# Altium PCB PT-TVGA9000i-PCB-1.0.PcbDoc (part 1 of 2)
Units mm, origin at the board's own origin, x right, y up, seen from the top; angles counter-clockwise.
Board outline 80.1 x 47 mm, 4 copper layers (Top Layer, Layer 1, Layer 2, Bottom Layer), stack 0.603 mm thick; 67 components, 130 nets, 468 pads, 340 vias.
Unrouted connection lines stored in the file: 9.
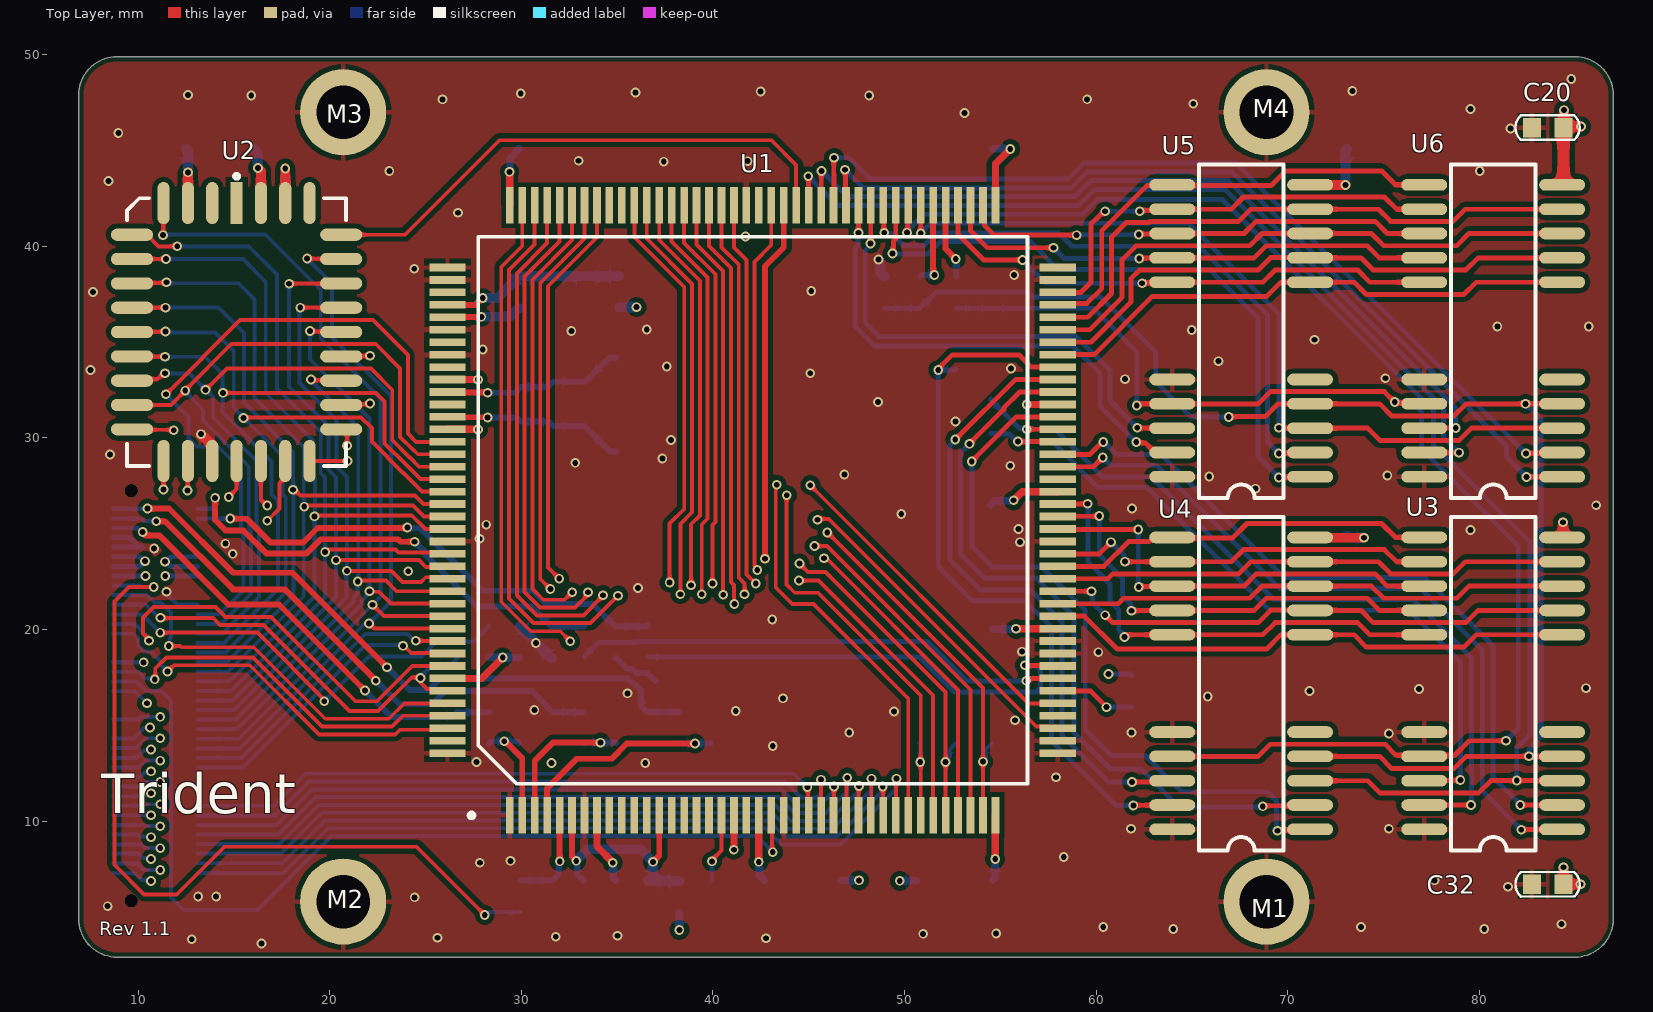
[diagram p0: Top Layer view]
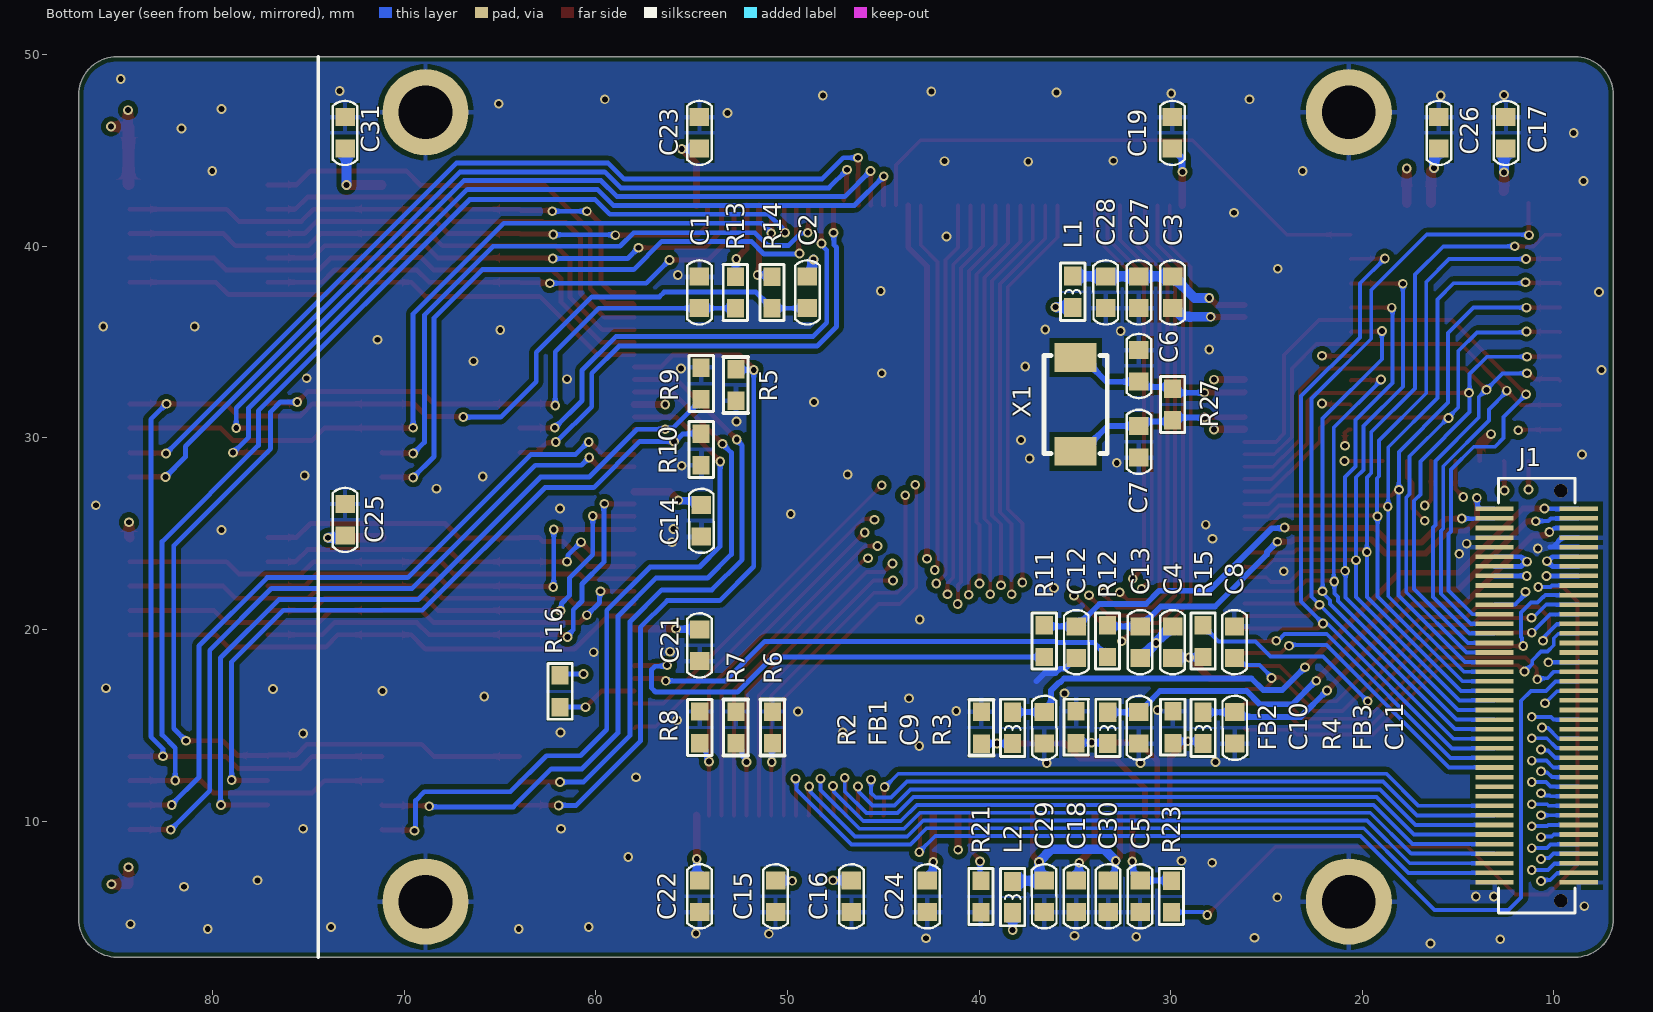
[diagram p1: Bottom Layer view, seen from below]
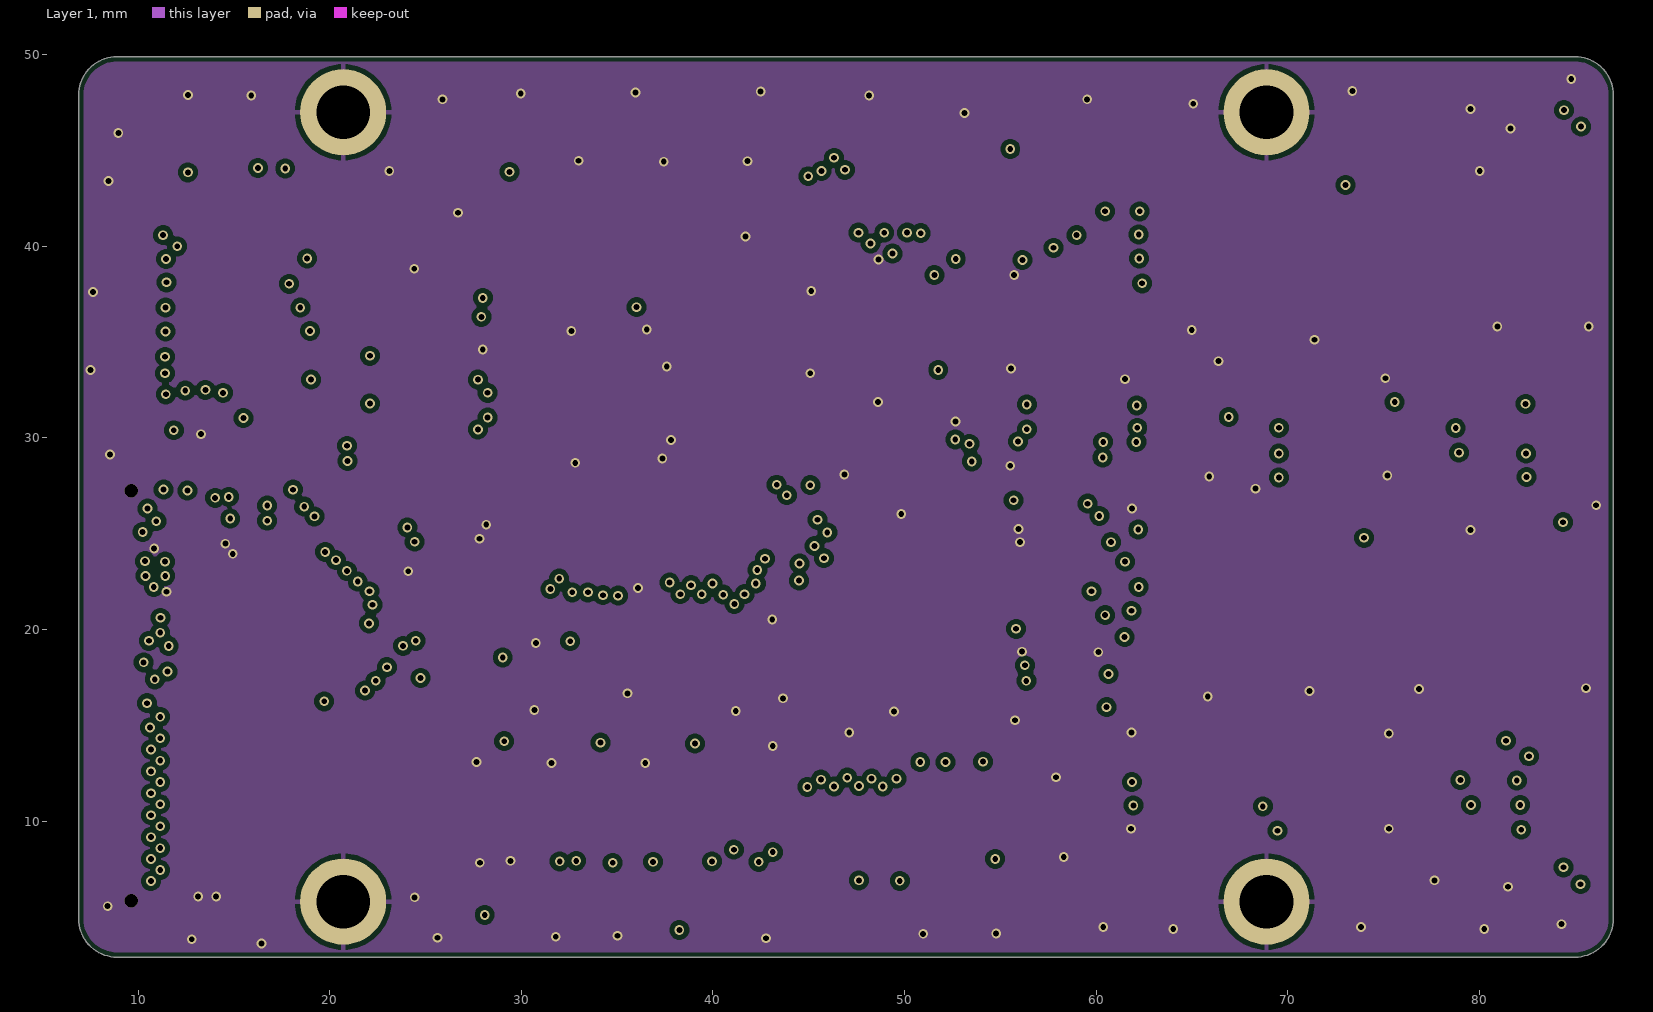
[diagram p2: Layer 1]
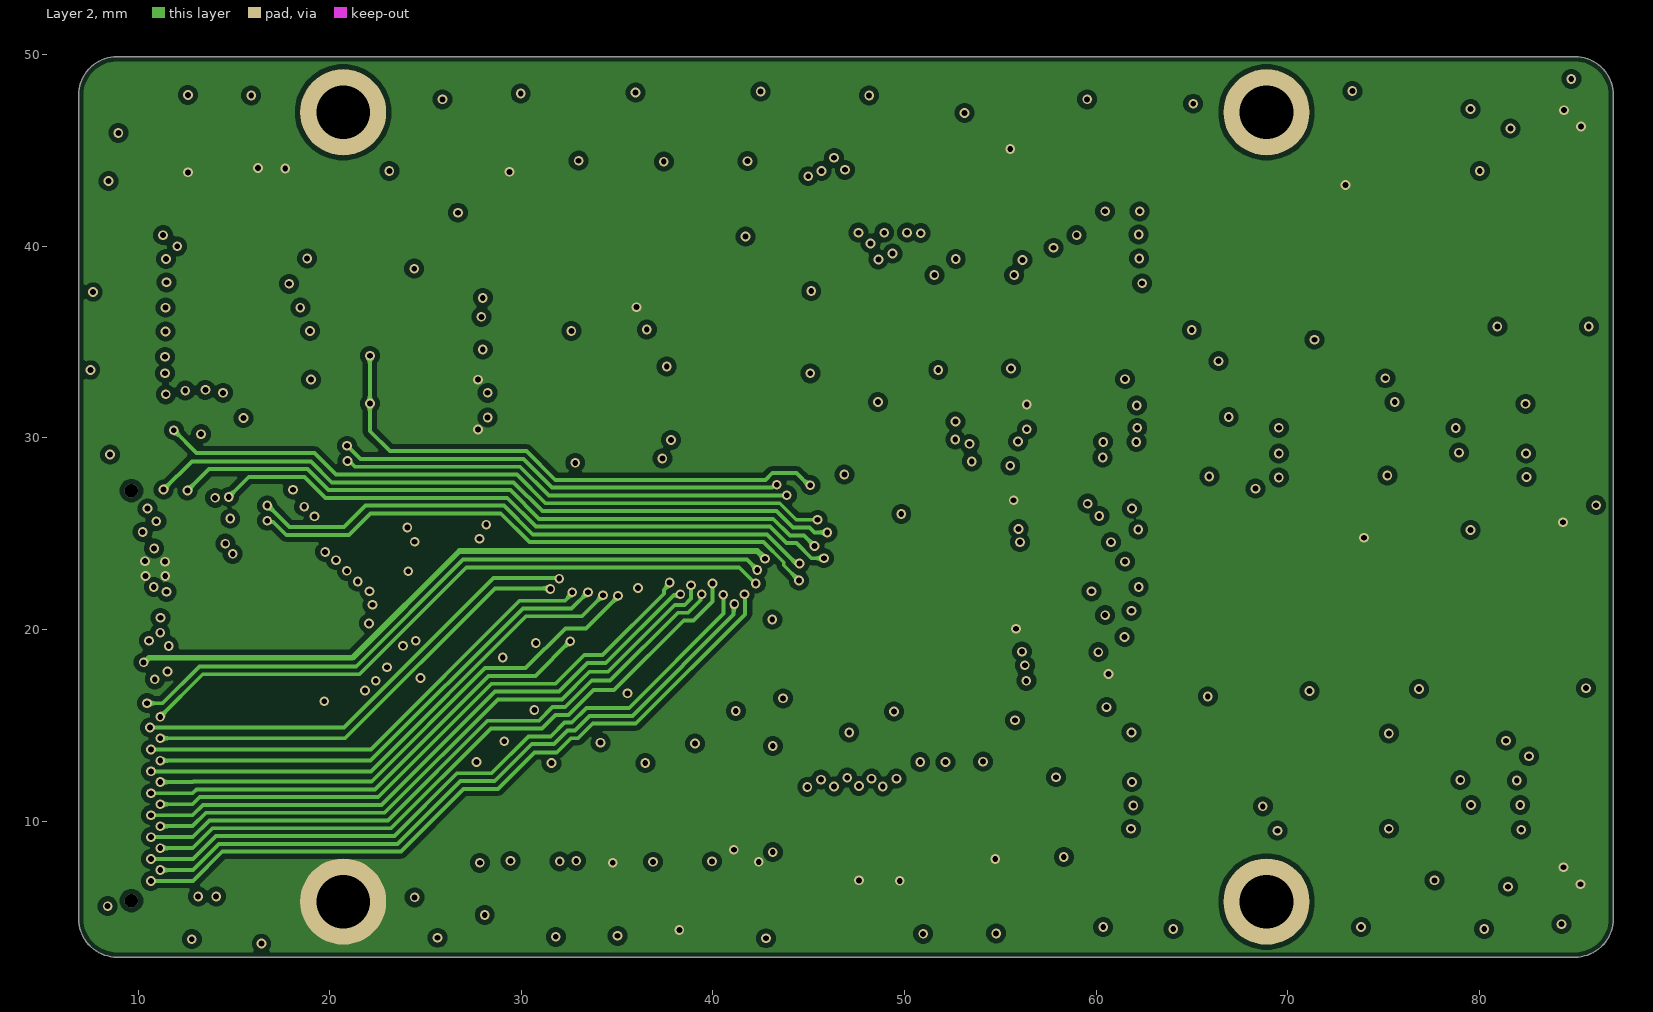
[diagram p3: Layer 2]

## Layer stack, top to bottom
Top Solder: solder mask 0.0102, Solder Resist, Dk 3.5
Top Layer: signal copper 0.0356
Dielectric 2: prepreg 0.0711, PP-006, Dk 4.1
Layer 1: signal copper 0.035
Dielectric 1: dielectric 0.32, FR-4, Dk 4.8
Layer 2: signal copper 0.035
Dielectric 3: prepreg 0.0711, PP-006, Dk 4.1
Bottom Layer: signal copper 0.0356
Bottom Solder: solder mask 0.0102, Solder Resist, Dk 3.5

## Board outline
6.9,4.9 6.9,47.9 cw(c8.9,47.9) 8.9,49.9 85,49.9 cw(c85,47.9) 87,47.9 87,4.9 cw(c85,4.9) 85,2.9 8.9,2.9 cw(c8.9,4.9)

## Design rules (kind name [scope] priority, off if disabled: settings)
BoardOutlineClearance [All] p1: gap=0 ignorepadtopadclearanceinfootprint=FALSE except(0.254: Poly-OutlineEdge)
Clearance [All] p1: gap=0.203 ignorepadtopadclearanceinfootprint=TRUE except(0.254: Arc-Fill Arc-Poly Arc-Region Track-Fill Track-Poly Track-Region SMDPad-Fill SMDPad-Poly SMDPad-Region THPad-Fill THPad-Poly THPad-Region Via-Fill Via-Poly Via-Region Fill-Fill Fill-Poly Fill-Region Poly-Poly Poly-Region Region-Region)
ComponentClearance [All] p1: gap=0 collisioncheckmode=3 verticalgap=0 showdistances=FALSE
HoleSize [All] p1: absolutevalues=TRUE maxlimit=254 minlimit=0.025 maxpercent=80.000 minpercent=20.000
MinimumSolderMaskSliver [All] p1: minsoldermaskwidth=0
PolygonConnect [All] p1: thpad.connectstyle=Relief thpad.reliefconductorwidth=0.254 thpad.reliefentries=4 thpad.polygonreliefangle="90 Angle" thpad.airgapwidth=0.254 smdpad.connectstyle=Relief smdpad.reliefconductorwidth=0.254 smdpad.reliefentries=4 smdpad.polygonreliefangle="90 Angle" smdpad.airgapwidth=0.254 via.connectstyle=Direct via.reliefconductorwidth=0.254 via.reliefentries=4 via.polygonreliefangle="90 Angle" via.airgapwidth=0.254
RoutingVias [All] p1: holewidth=0.711 width=1.27 viastyle="Through Hole" minholewidth=0.305 minwidth=0.508 maxholewidth=0.711 maxwidth=1.27
SilkToSilkClearance [All] p1: silktosilkclearance=0
SilkToSolderMaskClearance [IsPad] p1: minsilkscreentomaskgap=0 clearancetoexposedcopper=TRUE
SolderMaskExpansion [All] p1: expansion=0.102 istentingtop=FALSE
Width [All] p1: maxlimit=5.08 minlimit=0.203 preferedwidth=0.254 midlayer1_maxwidth=1.27 midlayer2_maxwidth=1.27 minimp=50.000000 maximp=50.000000 favimp=50.000000
25 further rules are at their usual default settings.

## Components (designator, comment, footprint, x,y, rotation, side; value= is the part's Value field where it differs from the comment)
C1 "47pf" C0603 54.6,36.774 r90 bottom
C2 "47pf" C0603 48.963,36.774 r90 bottom
C3 "0.1uf" C0603 29.905,38.424 r270 bottom
C4 "47pf" C0603 29.896,20.167 r270 bottom
C5 "470pf" C0603 31.6,6.9 r270 bottom
C6 "5pf" C0603 31.659,34.586 r270 bottom
C7 "5pf" C0603 31.666,28.973 r90 bottom
C8 "47pf" C0603 26.67,18.517 r90 bottom
C9 "47pf" C0603 36.597,15.696 r270 bottom
C10 "47pf" C0603 31.659,15.696 r270 bottom
C11 "47pf" C0603 26.652,15.696 r270 bottom
C12 "47pf" C0603 34.925,20.167 r270 bottom
C13 "47pf" C0603 31.598,20.167 r270 bottom
C14 "0.1uf" C0603 54.5,26.5 r270 bottom
C15 "10uf" C0603 50.629,6.9 r270 bottom
C16 "10uf" C0603 46.665,6.9 r270 bottom
C17 "10uf" C0603 12.5,45.1 r90 bottom
C18 "0.1uf" C0603 34.933,6.9 r270 bottom
C19 "0.1uf" C0603 29.911,45.1 r90 bottom
C20 "0.1uf" C0603 84.4,46.2 r180 top
C21 "0.1uf" C0603 54.594,20 r270 bottom
C22 "0.1uf" C0603 54.594,6.9 r270 bottom
C23 "0.1uf" C0603 54.6,45.1 r90 bottom
C24 "0.1uf" C0603 42.7,6.9 r270 bottom
C25 "0.1uf" C0603 73.1,24.9 r90 bottom
C26 "0.1uf" C0603 16,45.1 r90 bottom
C27 "0.1uf" C0603 31.659,38.424 r270 bottom
C28 "10uf" C0603 33.39,38.424 r270 bottom
C29 "0.1uf" C0603 36.6,6.9 r270 bottom
C30 "10uf" C0603 33.267,6.9 r270 bottom
C31 "0.1uf" C0603 73.1,45.1 r90 bottom
C32 "0.1uf" C0603 84.4,6.7 r180 top
FB1 "68R 100MHz" L0603 38.253,14.865 r270 bottom
FB2 "68R 100Mhz" L0603 33.281,14.865 r270 bottom
FB3 "68R 100Mhz" L0603 28.308,14.865 r270 bottom
J1 "CON40x2" BTB0.5-80P 8.9,6.8 r90 bottom locked
L1 "4.7uH" L0603 35.117,37.63 r270 bottom
L2 "4.7uH" L0603 38.253,6.037 r270 bottom
M1 "CON1" M2.5 68.9,5.8 r0 top locked
M2 "CON1" M2.5 20.7,5.8 r0 top locked
M3 "CON1" M2.5 20.7,47 r0 top locked
M4 "CON1" M2.5 68.9,47 r0 top
R2 "75" R0603 39.884,15.702 r270 bottom
R3 "75" R0603 34.937,15.728 r270 bottom
R4 "75" R0603 29.892,15.728 r270 bottom
R5 "4.7k" R0603 52.7,33.6 r270 bottom
R6 "4.7k" R0603 50.787,14.071 r90 bottom
R7 "4.7k" R0603 52.7,14.071 r90 bottom
R8 "4.7k" R0603 54.585,14.072 r90 bottom
R9 "4.7k" R0603 54.508,32.026 r90 bottom
R10 "4.7k" R0603 54.508,30.226 r270 bottom
R11 "33" R0603 36.601,18.567 r90 bottom
R12 "33" R0603 33.299,18.567 r90 bottom
R13 "33" R0603 52.725,36.773 r90 bottom
R14 "33" R0603 50.813,36.773 r90 bottom
R15 "75" R0603 28.309,18.567 r90 bottom
R16 "4.7k" R0603 61.874,15.951 r90 bottom
R21 "150" R0603 39.91,5.249 r90 bottom
R23 "1k" R0603 29.965,6.9 r270 bottom
R27 "1M" R0603 29.903,30.929 r90 bottom
U1 "TVGA9000i" QFP160 29.4,10.3 r90 top locked
U2 "29C512_PLCC32" PLCC32S 15.139,42.261 r0 top
U3 "MT4C4256" SOJ-20 84.334,9.568 r180 top locked
U4 "MT4C4256" SOJ-20 71.177,9.568 r180 top locked
U5 "MT4C4256" SOJ-20 71.177,27.972 r180 top locked
U6 "MT4C4256" SOJ-20 84.334,27.972 r180 top locked
X1 "40M" 5032 33.313,29.195 r90 bottom

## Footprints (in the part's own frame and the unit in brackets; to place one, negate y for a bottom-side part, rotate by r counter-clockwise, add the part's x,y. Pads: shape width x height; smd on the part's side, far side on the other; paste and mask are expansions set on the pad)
5032 [mm]
  rect 1.5x2.2 smd: 1(0.108,1.651) 2(5.008,1.651)
  silkscreen extent 0,0 5.11,3.3
BTB0.5-80P [mm]
  rect 0.24x2 smd: 1(0,-0.2) 2(0,4.2) 3(0.5,-0.2) 4(0.5,4.2) 5(1,-0.2) 6(1,4.2) 7(1.5,-0.2) 8(1.5,4.2) 9(2,-0.2) 10(2,4.2) 11(2.5,-0.2) 12(2.5,4.2) 13(3,-0.2) 14(3,4.2) 15(3.5,-0.2) 16(3.5,4.2) 17(4,-0.2) 18(4,4.2) 19(4.5,-0.2) 20(4.5,4.2) 21(5,-0.2) 22(5,4.2) 23(5.5,-0.2) 24(5.5,4.2) 25(6,-0.2) 26(6,4.2) 27(6.5,-0.2) 28(6.5,4.2) 29(7,-0.2) 30(7,4.2) 31(7.5,-0.2) 32(7.5,4.2) 33(8,-0.2) 34(8,4.2) 35(8.5,-0.2) 36(8.5,4.2) 37(9,-0.2) 38(9,4.2) 39(9.5,-0.2) 40(9.5,4.2) 41(10,-0.2) 42(10,4.2) 43(10.5,-0.2) 44(10.5,4.2) 45(11,-0.2) 46(11,4.2) 47(11.5,-0.2) 48(11.5,4.2) 49(12,-0.2) 50(12,4.2) 51(12.5,-0.2) 52(12.5,4.2) 53(13,-0.2) 54(13,4.2) 55(13.5,-0.2) 56(13.5,4.2) 57(14,-0.2) 58(14,4.2) 59(14.5,-0.2) 60(14.5,4.2) 61(15,-0.2) 62(15,4.2) 63(15.5,-0.2) 64(15.5,4.2) 65(16,-0.2) 66(16,4.2) 67(16.5,-0.2) 68(16.5,4.2) 69(17,-0.2) 70(17,4.2) 71(17.5,-0.2) 72(17.5,4.2) 73(18,-0.2) 74(18,4.2) 75(18.5,-0.2) 76(18.5,4.2) 77(19,-0.2) 78(19,4.2) 79(19.5,-0.2) 80(19.5,4.2)
  silkscreen extent -1.6,0 21.1,4
C0603 [mil]
  rect 37.01x40 smd: 1(0,0)
  rect 37x40 smd: 2(64.98,0)
  silkscreen extent -34,-25 98,25
L0603 [mm]
  rect 1x0.9 smd: 1(-0.82,0) 2(0.82,0)
  silkscreen extent -1.5,-0.64 1.5,0.64
M2.5 [mm]
  round 4.5 hole 2.8: 1(0,0)
PLCC32S [mil]
  rect 25x86.61 smd: 1(0,0)
  oval 25x86.61 smd: 2(-50,0) 3(-100,0) 4(-150,0) 14(-150,-530) 15(-100,-530) 16(-50,-530) 17(0,-530) 18(50,-530) 19(100,-530) 20(150,-530) 30(150,0) 31(100,0) 32(50,0)
  oval 86.61x25 smd: 5(-215,-65) 6(-215,-115) 7(-215,-165) 8(-215,-215) 9(-215,-265) 10(-215,-315) 11(-215,-365) 12(-215,-415) 13(-215,-465) 21(215,-465) 22(215,-415) 23(215,-365) 24(215,-315) 25(215,-265) 26(215,-215) 27(215,-165) 28(215,-115) 29(215,-65)
  silkscreen extent -225,-540 225,60
QFP160 [mm] "160-Pin Plastic Quad Flat Pack (PQFP)"
  rect 1.9x0.4 smd: 1(0,0) 2(0,-0.65) 3(0,-1.3) 4(0,-1.95) 5(0,-2.6) 6(0,-3.25) 7(0,-3.9) 8(0,-4.55) 9(0,-5.2) 10(0,-5.85) 11(0,-6.5) 12(0,-7.15) 13(0,-7.8) 14(0,-8.45) 15(0,-9.1) 16(0,-9.75) 17(0,-10.4) 18(0,-11.05) 19(0,-11.7) 20(0,-12.35) 21(0,-13) 22(0,-13.65) 23(0,-14.3) 24(0,-14.95) 25(0,-15.6) 26(0,-16.25) 27(0,-16.9) 28(0,-17.55) 29(0,-18.2) 30(0,-18.85) 31(0,-19.5) 32(0,-20.15) 33(0,-20.8) 34(0,-21.45) 35(0,-22.1) 36(0,-22.75) 37(0,-23.4) 38(0,-24.05) 39(0,-24.7) 40(0,-25.35) 81(31.85,-25.35) 82(31.85,-24.7) 83(31.85,-24.05) 84(31.85,-23.4) 85(31.85,-22.75) 86(31.85,-22.1) 87(31.85,-21.45) 88(31.85,-20.8) 89(31.85,-20.15) 90(31.85,-19.5) 91(31.85,-18.85) 92(31.85,-18.2) 93(31.85,-17.55) 94(31.85,-16.9) 95(31.85,-16.25) 96(31.85,-15.6) 97(31.85,-14.95) 98(31.85,-14.3) 99(31.85,-13.65) 100(31.85,-13) 101(31.85,-12.35) 102(31.85,-11.7) 103(31.85,-11.05) 104(31.85,-10.4) 105(31.85,-9.75) 106(31.85,-9.1) 107(31.85,-8.45) 108(31.85,-7.8) 109(31.85,-7.15) 110(31.85,-6.5) 111(31.85,-5.85) 112(31.85,-5.2) 113(31.85,-4.55) 114(31.85,-3.9) 115(31.85,-3.25) 116(31.85,-2.6) 117(31.85,-1.95) 118(31.85,-1.3) 119(31.85,-0.65) 120(31.85,0)
  rect 0.4x1.9 smd: 41(3.25,-28.6) 42(3.9,-28.6) 43(4.55,-28.6) 44(5.2,-28.6) 45(5.85,-28.6) 46(6.5,-28.6) 47(7.15,-28.6) 48(7.8,-28.6) 49(8.45,-28.6) 50(9.1,-28.6) 51(9.75,-28.6) 52(10.4,-28.6) 53(11.05,-28.6) 54(11.7,-28.6) 55(12.35,-28.6) 56(13,-28.6) 57(13.65,-28.6) 58(14.3,-28.6) 59(14.95,-28.6) 60(15.6,-28.6) 61(16.25,-28.6) 62(16.9,-28.6) 63(17.55,-28.6) 64(18.2,-28.6) 65(18.85,-28.6) 66(19.5,-28.6) 67(20.15,-28.6) 68(20.8,-28.6) 69(21.45,-28.6) 70(22.1,-28.6) 71(22.75,-28.6) 72(23.4,-28.6) 73(24.05,-28.6) 74(24.7,-28.6) 75(25.35,-28.6) 76(26,-28.6) 77(26.65,-28.6) 78(27.3,-28.6) 79(27.95,-28.6) 80(28.6,-28.6) 121(28.6,3.25) 122(27.95,3.25) 123(27.3,3.25) 124(26.65,3.25) 125(26,3.25) 126(25.35,3.25) 127(24.7,3.25) 128(24.05,3.25) 129(23.4,3.25) 130(22.75,3.25) 131(22.1,3.25) 132(21.45,3.25) 133(20.8,3.25) 134(20.15,3.25) 135(19.5,3.25) 136(18.85,3.25) 137(18.2,3.25) 138(17.55,3.25) 139(16.9,3.25) 140(16.25,3.25) 141(15.6,3.25) 142(14.95,3.25) 143(14.3,3.25) 144(13.65,3.25) 145(13,3.25) 146(12.35,3.25) 147(11.7,3.25) 148(11.05,3.25) 149(10.4,3.25) 150(9.75,3.25) 151(9.1,3.25) 152(8.45,3.25) 153(7.8,3.25) 154(7.15,3.25) 155(6.5,3.25) 156(5.85,3.25) 157(5.2,3.25) 158(4.55,3.25) 159(3.9,3.25) 160(3.25,3.25)
  silkscreen extent -0.12,-27.03 30.2,2.12
R0603 [mil]
  rect 38x35 smd: 1(0,0) 2(65,0)
  silkscreen extent -25,-25 90,25
SOJ-20 [mm] "薄贴片"
  oval 2.4x0.61 smd: 1(0,0) 2(0,-1.27) 3(0,-2.54) 4(0,-3.81) 5(0,-5.08) 6(0,-10.16) 7(0,-11.43) 8(0,-12.7) 9(0,-13.97) 10(0,-15.24) 11(7.2,-15.24) 12(7.2,-13.97) 13(7.2,-12.7) 14(7.2,-11.43) 15(7.2,-10.16) 16(7.2,-5.08) 17(7.2,-3.81) 18(7.2,-2.54) 19(7.2,-1.27) 20(7.2,0)
  silkscreen extent 1.4,-16.3 5.8,1.1

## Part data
C1 C2: library part 0CAP
C3 C4 C5 C6 C7 C8 C9 C10 C11 C12 C13 C14 C15 C16 C17 C18 C19 C20 C21 C22 C23 C24 C25 C26 C27 C28 C29 C30 C31 C32: library part CAP
FB1 FB2 FB3 L1 L2: library part L
R2 R3 R4 R5 R6 R7 R8 R9 R10 R11 R12 R13 R14 R15 R16 R21 R23 R27: library part RES2
X1: library part CRYSTAL

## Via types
v1: diameter 0.508, hole 0.305, Top Layer to Bottom Layer, tented both sides, 338 vias
v2: diameter 0.7, hole 0.7, Top Layer to Bottom Layer, 2 vias

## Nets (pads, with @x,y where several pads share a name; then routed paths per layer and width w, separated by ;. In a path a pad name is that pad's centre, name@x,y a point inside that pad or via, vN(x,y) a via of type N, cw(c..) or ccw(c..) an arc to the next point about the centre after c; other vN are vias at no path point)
A0: J1.58 U1.135 | length 36.8
  Top Layer w0.203: v1(11.448,32.279) 15.321,36.152 22.268,36.152 24.079,34.341 24.079,30.226 24.505,29.8 U1.135@26.15,29.8
  Bottom Layer w0.203: v1(11.448,32.279) 12.624,31.103 12.624,29.997 13.081,29.54 14.183,29.54 15.367,28.356 15.367,25.111 15.494,24.984 15.494,22.047 14.246,20.799 J1.58@13.1,20.8 J1.58@13.1,20.8
A1: J1.56 U1.136 U2.12 | length 37.7
  Top Layer w0.203: U2.12@9.678,31.72 11.711,31.72 v1(12.462,32.471) ; v1@12.446,32.487 14.859,34.9 22.403,34.9 23.673,33.63 23.673,30.058 24.337,29.394 24.351,29.394 24.594,29.15 U1.136@26.15,29.15
  Bottom Layer w0.203: v1(12.462,32.471) 12.462,32.42 13.386,31.496 13.386,30.912 15.773,28.524 15.773,25.28 15.9,25.153 15.9,21.87 14.33,20.3 J1.56@13.1,20.3
A2: J1.54 U1.137 U2.11 | length 37.1
  Top Layer w0.203: U2.11@9.678,32.99 9.761,33.073 11.019,33.073 11.322,33.376 v1(11.405,33.376) ; v1(13.513,32.512) 14.63,33.63 22.149,33.63 23.266,32.512 23.266,29.889 24.169,28.987 24.182,28.987 24.669,28.5 U1.137@26.15,28.5
  Bottom Layer w0.203: v1(11.405,33.376) 12.675,33.376 13.525,32.525 13.919,32.131 13.919,31.065 16.18,28.804 16.18,25.448 16.307,25.321 16.307,21.702 14.405,19.8 J1.54@13.1,19.8
A3: J1.52 U1.138 U2.10 | length 37.8
  Top Layer w0.203: U2.10@9.678,34.26 9.688,34.25 11.394,34.25 v1(11.405,34.239) ; v1(14.431,32.356) 22.409,32.356 22.86,31.905 22.86,29.721 24,28.581 24.014,28.581 24.745,27.85 U1.138@26.15,27.85
  Bottom Layer w0.203: v1(11.405,34.239) 13.487,34.239 14.395,33.332 v1@14.395,32.34 ; J1.52@13.1,19.3 14.48,19.3 17.297,22.118 17.297,26.724 16.97,27.051 16.97,28.773 14.395,31.348 14.395,32.32 v1(14.431,32.356)
A4: J1.50 U1.139 U2.9 | length 38.1
  Top Layer w0.203: U2.9@9.678,35.53 9.693,35.545 11.415,35.545 v1(11.43,35.56) ; v1(15.494,31.039) 15.528,31.072 21.64,31.072 22.2,30.513 22.2,29.807 23.832,28.174 23.846,28.174 24.82,27.2 U1.139@26.15,27.2
  Bottom Layer w0.203: v1(11.43,35.56) 11.481,35.509 14.021,35.509 14.99,34.54 14.99,31.582 15.513,31.058 17.526,29.045 17.526,27.07 17.704,26.892 17.704,21.95 14.554,18.8 J1.50@13.1,18.8
A5: J1.48 U1.140 U2.8 | length 36
  Top Layer w0.203: U2.8@9.678,36.8 9.68,36.802 11.428,36.802 v1(11.43,36.805) ; v1(18.085,27.301) 18.167,27.301 18.468,27 24.445,27 24.895,26.55 U1.140@26.15,26.55
  Bottom Layer w0.203: v1(11.43,36.805) 14.199,36.805 15.517,35.486 15.517,31.848 18.092,29.273 18.092,27.308 v1(18.085,27.301) ; J1.48@13.1,18.3 14.629,18.3 18.11,21.781 18.11,27.283 v1@18.092,27.301
A6: J1.46 U1.141 U2.7 | length 38.3
  Top Layer w0.203: U2.7@9.678,38.07 9.706,38.098 11.453,38.098 v1(11.481,38.125) ; v1(18.669,26.416) 18.72,26.467 24.349,26.467 24.916,25.9 U1.141@26.15,25.9
  Bottom Layer w0.203: v1(11.481,38.125) 11.532,38.075 15.24,38.075 16.078,37.236 16.078,32.08 18.644,29.515 v1@18.644,26.416 ; J1.46@13.1,17.8 14.704,17.8 18.644,21.74 18.644,26.391 v1(18.669,26.416)
A7: J1.44 U1.142 U2.6 | length 40.2
  Top Layer w0.203: U2.6@9.678,39.34 9.68,39.342 11.453,39.342 v1(11.455,39.345) ; v1(19.202,25.908) 19.253,25.959 24.282,25.959 24.991,25.25 U1.142@26.15,25.25
  Bottom Layer w0.203: v1(11.455,39.345) 15.469,39.345 16.662,38.151 16.662,32.334 19.126,29.87 19.126,28.001 19.228,27.9 19.228,25.933 v1(19.202,25.908) 19.202,21.724 14.778,17.3 J1.44@13.1,17.3
A8: J1.42 U1.144 U2.5 | length 41.5
  Top Layer w0.203: U2.5@9.678,40.61 10.46,40.61 11.065,40.005 v1(12.04,40.005) ; v1(19.761,24.054) 19.844,24.054 19.971,24.181 23.444,24.181 23.597,24.028 26.072,24.028 U1.144@26.15,23.95
  Bottom Layer w0.203: v1(12.04,40.005) 15.773,40.005 17.247,38.532 17.247,32.588 19.533,30.302 19.533,28.17 19.761,27.941 v1(19.761,24.054) 19.736,24.028 19.761,24.003 19.761,21.708 14.853,16.8 J1.42@13.1,16.8
A9: J1.40 U1.145 U2.27 | length 35.5
  Top Layer w0.203: v1(17.882,38.049) 17.892,38.06 20.59,38.06 U2.27@20.6,38.07 ; v1(20.326,23.622) 24.663,23.622 25.014,23.271 26.121,23.271 U1.145@26.15,23.3
  Bottom Layer w0.203: J1.40@13.1,16.3 14.928,16.3 20.337,21.709 20.337,23.612 v1(20.326,23.622) ; v1(17.882,38.049) 17.882,32.674 19.939,30.616 19.939,28.338 20.326,27.951 20.326,23.632 v1@20.332,23.627
A10: J1.38 U1.146 U2.26 | length 34.2
  Top Layer w0.203: v1(18.466,36.805) 18.468,36.802 20.598,36.802 U2.26@20.6,36.8 ; v1(20.896,23.063) 23.216,23.063 23.8,22.479 24.765,22.479 25.014,22.728 26.072,22.728 U1.146@26.15,22.65
  Bottom Layer w0.203: J1.38@13.1,15.8 15.003,15.8 20.868,21.665 20.868,23.035 v1(20.896,23.063) ; v1(18.466,36.805) 18.415,36.754 18.415,32.868 20.345,30.937 20.345,28.506 20.896,27.956 20.896,23.091 v1@20.882,23.077
A11: J1.36 U1.147 U2.23 | length 29.9
  Top Layer w0.203: v1(19.026,33.047) 19.054,33.018 20.572,33.018 U2.23@20.6,32.99 ; v1(21.463,22.504) 21.514,22.555 22.936,22.555 23.491,22 U1.147@26.15,22
  Bottom Layer w0.203: J1.36@13.1,15.3 15.077,15.3 21.274,21.497 21.274,21.696 21.459,21.881 21.459,22.501 21.488,22.53 21.488,30.547 19.026,33.009 v1(19.026,33.047)
A12: J1.34 U1.148 U2.25 | length 33
  Top Layer w0.203: v1(18.974,35.585) 19.002,35.558 20.572,35.558 U2.25@20.6,35.53 ; v1(22.073,21.996) 22.098,21.996 22.123,21.971 22.581,21.971 23.202,21.35 U1.148@26.15,21.35
  Bottom Layer w0.203: J1.34@13.1,14.8 15.152,14.8 21.68,21.328 21.68,21.528 22.123,21.971 22.073,22.022 22.073,31.013 18.974,34.112 v1(18.974,35.585)
A13: J1.32 U1.149 U2.4 | length 45.2
  Top Layer w0.203: v1(11.303,40.589) 11.316,40.602 11.316,42.248 U2.4@11.329,42.261 ; v1(22.239,21.296) 22.836,20.7 U1.149@26.15,20.7
  Bottom Layer w0.203: v1(11.303,40.589) 11.328,40.615 16.637,40.615 19.533,37.719 19.533,35.179 22.657,32.055 22.657,21.714 v1(22.239,21.296) 15.243,14.3 J1.32@13.1,14.3
A14: J1.30 U1.150 U2.28 | length 39
  Top Layer w0.203: v1(18.821,39.37) 18.836,39.355 20.585,39.355 U2.28@20.6,39.34 ; v1(22.053,20.32) 22.056,20.317 22.076,20.317 22.343,20.05 U1.150@26.15,20.05
  Bottom Layer w0.203: J1.30@13.1,13.8 15.318,13.8 21.779,20.262 21.995,20.262 v1(22.053,20.32) ; v1(18.821,39.37) 20.117,38.074 20.117,35.255 23.19,32.182 23.19,21.457 v1@22.059,20.326
A15: J1.28 U1.151 | length 15.9
  Top Layer w0.203: v1(24.49,19.413) 24.496,19.406 26.144,19.406 U1.151@26.15,19.4
  Bottom Layer w0.203: J1.28@13.1,13.3 15.392,13.3 21.853,19.761 24.059,19.761 24.407,19.413 v1(24.49,19.413)
A16: J1.26 U1.152 | length 15.9
  Top Layer w0.203: v1(23.829,19.15) 23.89,19.15 24.255,18.786 26.114,18.786 U1.152@26.15,18.75
  Bottom Layer w0.203: J1.26@13.1,12.8 15.467,12.8 21.869,19.202 23.776,19.202 v1(23.829,19.15)
A17: J1.24
A18: J1.22
A19: J1.20
AEN: J1.43 U1.22 | length 49.3
  Top Layer w0.203: U1.22@43.05,10.3 43.09,10.26 43.09,8.422 v1(43.129,8.382)
  Bottom Layer w0.203: J1.43@8.7,17.3 8.718,17.282 9.912,17.282 10.405,16.789 11.201,16.789 11.709,16.281 11.709,6.02 12.37,5.359 16.231,5.359 20.091,9.22 42.291,9.22 v1(43.129,8.382)
ALE: J1.49
AVCC1: C3.1 C27.1 C28.1 L1.1 U1.124 | length 9.6
  Top Layer w0.305: U1.124@26.15,36.95 27.603,36.95 27.965,37.313 v1(27.991,37.313)
  Bottom Layer w0.508: v1(27.991,37.313) 28.756,37.313 29.867,38.424 C3.1@29.905,38.424 29.918,38.437 35.104,38.437 L1.1@35.117,38.45
AVCC2: C29.1 C30.1 L2.1 U1.6 U1.13 | length 13.2
  Top Layer w0.305: U1.6@32.65,10.3 32.65,8.142 v1(32.868,7.925) ; v1(36.881,7.874) 37.2,8.193 U1.13@37.2,10.3
  Bottom Layer w0.305: v1(32.868,7.925) 32.868,7.87 32.911,7.826 32.911,7.218 33.229,6.9 C30.1@33.267,6.9
  Bottom Layer w0.508: v1(32.868,7.925) 33.477,8.534 36.22,8.534 v1(36.881,7.874) 36.881,7.181 C29.1@36.854,7.154 ; C29.1@36.6,6.9 36.621,6.879 38.232,6.879 L2.1@38.253,6.857
BHE#: J1.41 U1.99 | length 56.7
  Top Layer w0.203: v1(42.32,23.111) 42.32,23.194 42.164,23.35 42.164,39.192 43.05,40.078 U1.99@43.05,42.15
  Layer 2 w0.203: v1(10.465,16.154) 11.278,16.154 13.195,18.072 21.385,18.072 26.961,23.647 41.783,23.647 v1@42.319,23.111
  Bottom Layer w0.203: J1.41@8.7,16.8 8.718,16.782 9.838,16.782 v1(10.465,16.154)
CAS*: C1.1 R13.1 U3.17 U4.17 U5.17 U6.17 | length 68.1
  Top Layer w0.254: v1(62.128,31.699) 62.197,31.699 62.28,31.782 U5.17@63.977,31.782 68.471,31.782 69.106,32.417 75.053,32.417 75.59,31.88 v1(75.59,31.877) 75.638,31.83 77.087,31.83 U6.17@77.134,31.782 ; U4.17@63.977,13.378 68.471,13.378 69.106,14.013 75.09,14.013 75.657,13.446 77.066,13.446 U3.17@77.134,13.378 77.18,13.424 78.715,13.424 79.49,14.199 v1(81.407,14.199)
  Bottom Layer w0.254: R13.1@52.725,36.773 59.848,36.773 62.128,34.493 v1(62.128,31.699) ; v1(75.59,31.877) 76.479,31.877 76.987,31.369 76.987,29.439 82.042,24.384 82.042,14.834 v1(81.407,14.199)
D0: J1.18 U1.25 | length 34.3
  Top Layer w0.203: v1(44.933,11.786) 44.966,11.752 44.966,10.334 U1.25@45,10.3
  Bottom Layer w0.203: J1.18@13.1,10.8 17.073,10.8 18.745,12.471 44.221,12.471 44.907,11.786 v1(44.933,11.786)
D1: J1.16 U1.26 | length 36.3
  Top Layer w0.203: v1(45.644,12.167) 45.647,12.163 45.647,10.303 U1.26@45.65,10.3
  Bottom Layer w0.203: J1.16@13.1,10.3 17.148,10.3 18.913,12.065 43.758,12.065 44.596,11.227 45.399,11.227 45.644,11.471 v1(45.644,12.167)
D2: J1.14 U1.27 | length 36.4
  Top Layer w0.203: U1.27@46.3,10.3 46.315,10.315 46.315,11.796 v1(46.33,11.811)
  Bottom Layer w0.203: J1.14@13.1,9.8 17.223,9.8 19.081,11.659 43.59,11.659 44.428,10.82 45.568,10.82 46.271,11.524 46.271,11.753 v1(46.33,11.811)
D3: J1.12 U1.28 | length 38.3
  Top Layer w0.203: U1.28@46.95,10.3 46.983,10.333 46.983,12.236 v1(47.015,12.268)
  Bottom Layer w0.203: J1.12@13.1,9.3 17.298,9.3 19.25,11.252 43.422,11.252 44.26,10.414 45.882,10.414 47.015,11.548 v1(47.015,12.268)
D4: J1.10 U1.29 | length 38.2
  Top Layer w0.203: U1.29@47.6,10.3 47.612,10.312 47.612,11.823 v1(47.625,11.835)
  Bottom Layer w0.203: J1.10@13.1,8.8 17.372,8.8 19.418,10.846 43.253,10.846 44.091,10.008 46.05,10.008 47.566,11.524 47.566,11.777 v1(47.625,11.835)
D5: J1.8 U1.30 | length 39.8
  Top Layer w0.203: U1.30@48.25,10.3 48.268,10.318 48.268,12.2 v1(48.285,12.217)
  Bottom Layer w0.203: J1.8@13.1,8.3 17.447,8.3 19.586,10.439 43.085,10.439 43.923,9.601 46.253,9.601 48.285,11.633 v1(48.285,12.217)
D6: J1.6 U1.31 | length 39.8
  Top Layer w0.203: v1(48.87,11.811) 48.885,11.796 48.885,10.315 U1.31@48.9,10.3
  Bottom Layer w0.203: J1.6@13.1,7.8 17.522,7.8 19.755,10.033 42.917,10.033 43.755,9.195 46.482,9.195 48.811,11.524 48.811,11.753 v1(48.87,11.811)
D7: J1.4 U1.32 | length 41.4
  Top Layer w0.203: U1.32@49.55,10.3 49.565,10.315 49.565,12.202 v1(49.581,12.217)
  Bottom Layer w0.203: J1.4@13.1,7.3 17.596,7.3 19.923,9.627 42.748,9.627 43.586,8.788 46.66,8.788 49.53,11.659 49.53,12.167 v1(49.581,12.217)
D8: J1.17 U1.110 | length 55.1
  Top Layer w0.203: U1.110@35.9,42.15 35.9,40.478 38.506,37.871 38.506,26.289 37.744,25.527 v1(37.744,22.454)
  Layer 2 w0.203: v1(11.151,10.881) 12.843,10.881 13.214,11.252 22.533,11.252 28.451,17.17 31.791,17.17 33.285,18.665 34.243,18.665 37.447,21.868 37.447,22.073 37.744,22.371 v1(37.744,22.454)
  Bottom Layer w0.203: J1.17@8.7,10.8 10.264,10.8 10.345,10.881 v1(11.151,10.881)
D9: J1.15 U1.109 | length 55.9
  Top Layer w0.203: U1.109@36.55,42.15 36.55,40.403 38.913,38.04 38.913,26.121 38.303,25.511 v1(38.303,21.844)
  Layer 2 w0.203: v1(10.668,10.308) 12.845,10.308 13.382,10.846 22.702,10.846 28.62,16.764 31.959,16.764 33.454,18.258 34.411,18.258 37.939,21.786 38.245,21.786 v1(38.303,21.844)
  Bottom Layer w0.203: J1.15@8.7,10.3 8.704,10.304 10.664,10.304 v1(10.668,10.308)
D10: J1.13 U1.108 | length 56.7
  Top Layer w0.203: U1.108@37.2,42.15 37.2,40.327 39.319,38.208 39.319,25.952 38.862,25.495 v1(38.862,22.314)
  Layer 2 w0.203: v1(11.151,9.736) 12.847,9.736 13.551,10.439 22.87,10.439 28.788,16.358 32.128,16.358 33.565,17.795 34.523,17.795 38.013,21.285 38.535,21.285 38.862,21.613 v1(38.862,22.314)
  Bottom Layer w0.203: J1.13@8.7,9.8 10.293,9.8 10.357,9.736 v1(11.151,9.736)
D11: J1.11 U1.107 | length 57.4
  Top Layer w0.203: U1.107@37.85,42.15 37.85,40.252 39.726,38.376 39.726,25.784 39.421,25.479 v1(39.421,21.844)
  Layer 2 w0.203: v1(10.668,9.164) 12.85,9.164 13.719,10.033 23.038,10.033 28.245,15.24 30.915,15.24 31.626,15.951 32.296,15.951 33.679,17.334 34.637,17.334 38.181,20.879 38.71,20.879 39.362,21.532 39.362,21.786 v1(39.421,21.844)
  Bottom Layer w0.203: J1.11@8.7,9.3 10.008,9.3 10.109,9.198 10.633,9.198 v1(10.668,9.164)
D12: J1.9 U1.106 | length 58.1
  Top Layer w0.203: U1.106@38.5,42.15 38.5,40.177 40.132,38.545 40.132,25.616 39.98,25.463 v1(39.98,22.402)
  Layer 2 w0.203: v1(11.151,8.591) 12.852,8.591 13.887,9.627 23.207,9.627 28.414,14.834 31.083,14.834 31.794,15.545 32.464,15.545 33.761,16.841 34.85,16.841 38.481,20.472 38.989,20.472 39.98,21.463 v1(39.98,22.402)
  Bottom Layer w0.203: J1.9@8.7,8.8 8.718,8.782 10.167,8.782 10.357,8.591 v1(11.151,8.591)
D13: J1.7 U1.105 | length 59.2
  Top Layer w0.203: U1.105@39.15,42.15 39.15,40.101 40.538,38.713 v1(40.538,21.819)
  Layer 2 w0.203: v1(10.668,8.019) 12.854,8.019 14.056,9.22 23.375,9.22 26.652,12.497 28.448,12.497 30.378,14.427 31.54,14.427 32.252,15.138 32.633,15.138 33.395,15.9 35.636,15.9 40.564,20.828 40.564,21.793 v1(40.538,21.819)
  Bottom Layer w0.203: J1.7@8.7,8.3 10.029,8.3 10.252,8.077 10.61,8.077 v1(10.668,8.019)
D14: J1.5 U1.104 | length 60
  Top Layer w0.203: U1.104@39.8,42.15 39.8,40.026 40.945,38.881 40.945,22.488 41.097,22.336 41.097,21.361 v1(41.123,21.336)
  Layer 2 w0.203: v1(11.151,7.446) 12.856,7.446 14.224,8.814 23.543,8.814 26.82,12.09 28.616,12.09 30.547,14.021 31.709,14.021 32.42,14.732 32.801,14.732 33.563,15.494 35.805,15.494 41.088,20.777 41.088,21.301 v1(41.123,21.336)
  Bottom Layer w0.203: J1.5@8.7,7.8 8.718,7.782 9.973,7.782 10.308,7.446 v1(11.151,7.446)
D15: J1.3 U1.103 | length 60.8
  Top Layer w0.203: U1.103@40.45,42.15 40.45,39.951 41.351,39.05 41.351,22.715 41.656,22.411 v1(41.656,21.844)
  Layer 2 w0.203: v1(10.668,6.874) 12.859,6.874 14.392,8.407 23.712,8.407 26.988,11.684 28.785,11.684 30.69,13.589 31.852,13.589 32.588,14.326 32.969,14.326 33.731,15.088 35.973,15.088 41.681,20.796 41.681,21.819 v1(41.656,21.844)
  Bottom Layer w0.203: J1.3@8.7,7.3 8.718,7.282 9.841,7.282 10.19,6.932 10.61,6.932 v1(10.668,6.874)
GND: C1.2 C2.2 C4.1 C5.2 C6.1 C7.1 C8.2 C9.2 C10.2 C11.2 C12.2 C13.2 C14.2 C15.2 C16.2 C17.2 C18.2 C19.2 C20.2 C21.2 C22.2 C23.2 C24.2 C25.2 C26.2 C27.2 C28.2 C29.2 C30.2 C31.2 C32.2 J1.1 J1.2 J1.60 J1.71 J1.72 J1.73 J1.74 M1.1 M2.1 M3.1 M4.1 R2.1 R3.1 R4.1 R5.2 R6.2 R7.2 R8.2 R9.2 R10.2 R21.1 U1.1 U1.7 U1.23 U1.41 U1.42 U1.49 U1.50 U1.58 U1.79 U1.80 U1.101 U1.121 U1.122 U1.126 U1.128 U1.143 U1.160 U2.16 U3.16 U3.20 U4.16 U4.20 U5.16 U5.20 U6.16 U6.20 | length 12.7
  Top Layer w0.229: U2.16@13.869,28.799 U2.16@13.869,29.611
  Top Layer w0.508: v1(13.284,30.201) 13.869,29.616 U2.16@13.869,29.611
  Bottom Layer w0.229: v1(11.481,21.971) 11.534,21.918 11.534,21.797 12.025,21.306 13.094,21.306 J1.60@13.1,21.3
  Bottom Layer w0.254: J1.71@8.7,24.3 10.066,24.3 ; J1.73@8.7,24.8 9.566,24.8 10.066,24.3 ; 10.211,24.308 10.203,24.3 10.066,24.3
  Bottom Layer w0.305: C12.2@34.925,18.516 34.963,18.516 35.521,17.958 35.781,17.958 36.01,17.729 36.576,17.729 37.008,17.297
  Bottom Layer w0.508: C4.1@29.896,20.167 29.934,20.167 30.759,19.341 v1(30.759,19.304) 30.772,19.304 31.559,18.516 C13.2@31.598,18.516 ; v1(48.641,39.319) 48.709,39.251 48.709,38.64 48.925,38.424 C2.2@48.963,38.424
  other v1: 16.434,3.607 12.802,3.835 42.774,3.886 25.629,3.912 31.801,3.962 35.027,4.013 50.978,4.115 54.788,4.14 64.033,4.369 80.264,4.369 60.376,4.47 73.838,4.47 84.303,4.623 8.407,5.563 24.435,6.02 13.132,6.071 14.072,6.071 81.509,6.579 77.673,6.909 27.838,7.823 29.439,7.925 58.318,8.128 61.824,9.601 75.286,9.601 57.912,12.294 31.572,13.03 36.474,13.03 27.661,13.081 43.129,13.919 75.286,14.58 47.117,14.63 61.849,14.63 55.777,15.264 49.454,15.723 41.199,15.748 30.683,15.799 43.663,16.408 65.837,16.51 35.54,16.67 71.145,16.789 76.86,16.891 85.573,16.942 60.122,18.821 56.134,18.847 43.104,20.523 36.093,22.174 24.101,23.043 14.935,23.952 10.834,24.23 14.554,24.486 56.032,24.562 27.813,24.74 79.553,25.197 55.956,25.248 28.169,25.476 49.835,26.035 61.874,26.314 86.106,26.492 68.326,27.356 65.913,27.991 75.209,28.042 46.863,28.092 55.524,28.55 32.817,28.702 37.363,28.931 8.534,29.134 37.821,29.896 52.66,30.855 48.616,31.877 61.519,33.071 75.103,33.117 45.085,33.376 7.518,33.553 55.566,33.623 37.592,33.731 66.396,34.011 27.991,34.62 71.399,35.128 32.614,35.585 64.999,35.636 36.551,35.662 80.95,35.814 85.725,35.814 7.645,37.617 45.136,37.668 55.728,38.506 24.409,38.837 41.707,40.513 26.695,41.758 8.458,43.409 23.114,43.942 80.035,43.942 37.44,44.425 41.808,44.45 32.995,44.475 8.966,45.923 81.636,46.152 53.137,46.965 79.553,47.168 65.075,47.447 25.883,47.676 59.538,47.676 15.9,47.879 48.158,47.879 12.598,47.904 29.972,47.981 35.966,48.031 42.494,48.082 73.381,48.108 84.811,48.743
  other v2: 9.65,5.85 9.65,27.25
HSYNC: R11.1 U1.48 | length 24.9
  Top Layer w0.254: v1(56.286,18.136) 56.304,18.118 57.982,18.118 U1.48@58,18.1
  Bottom Layer w0.254: R11.1@36.601,18.567 50.775,18.567 52.603,16.739 56.896,16.739 57.099,16.942 57.099,17.907 56.919,18.087 56.335,18.087 v1(56.286,18.136)
HSYNC1: C12.1 J1.78 R11.2 | length 26.5
  Top Layer w0.305: v1(14.808,25.793) 14.82,25.781 15.672,25.781 16.916,24.536 18.605,24.536 19.367,25.298 24.027,25.298 v1(24.052,25.324)
  Bottom Layer w0.229: J1.78@13.107,25.794 14.21,25.794 14.211,25.793 v1(14.808,25.793)
  Bottom Layer w0.305: v1(24.052,25.324) 24.091,25.285 24.728,25.285 27.991,22.022 30.607,22.022 31.293,21.336 33.718,21.336 34.887,20.167 C12.1@34.925,20.167 36.55,20.167 R11.2@36.601,20.218
IOCS16#: J1.33
IOR#: J1.55 U1.153 | length 22.6
  Top Layer w0.203: v1(10.564,19.414) 10.564,19.496 10.262,19.798 10.262,20.628 10.806,21.172 14.032,21.172 14.554,20.65 16.942,20.65 21.336,16.256 22.463,16.256 24.307,18.1 U1.153@26.15,18.1
  Bottom Layer w0.203: J1.55@8.7,20.3 8.718,20.282 9.844,20.282 10.505,19.621 10.505,19.472 v1(10.564,19.414)
IORDY: J1.45 U1.157 | length 20.1
  Top Layer w0.203: v1(10.871,17.399) 10.894,17.422 10.894,17.958 11.478,18.542 15.993,18.542 19.599,14.935 23.25,14.935 23.815,15.5 U1.157@26.15,15.5
  Bottom Layer w0.203: J1.45@8.7,17.8 9.985,17.8 10.327,17.457 10.813,17.457 v1(10.871,17.399)
IOW#: J1.57 R15.2 | length 23.2
  Top Layer w0.203: v1(11.151,19.837) 16.231,19.837 v1@19.763,16.305
  Bottom Layer w0.203: J1.57@8.7,20.8 8.718,20.782 10.206,20.782 v1(11.151,19.837) ; v1(19.712,16.255) 22.05,18.593 23.419,18.593 23.42,18.591 24.789,18.591 25.578,19.38 27.509,19.38 28.309,20.18 R15.2@28.309,20.218
LA17: J1.31 U1.113 | length 47.6
  Top Layer w0.203: v1(31.979,22.657) 31.394,23.241 31.394,37.922 33.95,40.478 U1.113@33.95,42.15
  Layer 2 w0.203: v1(10.617,14.884) 20.752,14.884 28.55,22.682 31.953,22.682 v1(31.979,22.657)
  Bottom Layer w0.203: J1.31@8.7,14.3 8.718,14.318 9.772,14.318 10.305,14.851 10.584,14.851 v1(10.617,14.884)
LA18: J1.29 U1.114 | length 47.5
  Top Layer w0.203: v1(31.518,22.115) 30.988,22.645 30.988,38.091 33.3,40.403 U1.114@33.3,42.15
  Layer 2 w0.203: v1(11.151,14.326) 20.803,14.326 28.626,22.149 31.484,22.149 v1(31.518,22.115)
  Bottom Layer w0.203: J1.29@8.7,13.8 8.718,13.818 9.865,13.818 10.373,14.326 v1(11.151,14.326)
LA19: J1.27 U1.115 | length 50.9
  Top Layer w0.203: U1.115@32.65,42.15 32.65,40.327 30.582,38.259 30.582,22.123 31.149,21.556 32.264,21.556 32.653,21.946 v1(32.664,21.946)
  Layer 2 w0.203: v1(10.668,13.743) 22.151,13.743 29.913,21.505 32.275,21.505 32.664,21.895 v1(32.664,21.946)
  Bottom Layer w0.203: J1.27@8.7,13.3 9.922,13.3 10.307,13.685 10.61,13.685 v1(10.668,13.743)
LA20: J1.25 U1.116 | length 53.6
  Top Layer w0.203: U1.116@32,42.15 32,40.252 30.175,38.427 30.175,21.955 30.981,21.15 32.808,21.15 33.477,21.819 v1(33.477,21.946)
  Layer 2 w0.203: v1(11.151,13.157) 22.139,13.157 30.081,21.099 32.631,21.099 v1(33.477,21.946)
  Bottom Layer w0.203: J1.25@8.7,12.8 10.031,12.8 10.389,13.157 v1(11.151,13.157)
LA21: J1.23 U1.117 | length 55.9
  Top Layer w0.203: U1.117@31.35,42.15 31.35,40.177 29.769,38.596 29.769,21.787 30.812,20.743 33.24,20.743 34.239,21.742 34.239,21.768 v1(34.265,21.793)
  Layer 2 w0.203: v1(10.668,12.598) 22.155,12.598 30.249,20.693 33.164,20.693 v1(34.265,21.793)
  Bottom Layer w0.203: J1.23@8.7,12.3 10.106,12.3 10.346,12.54 10.61,12.54 v1(10.668,12.598)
